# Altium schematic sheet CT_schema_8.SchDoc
size 254 x 194 mm
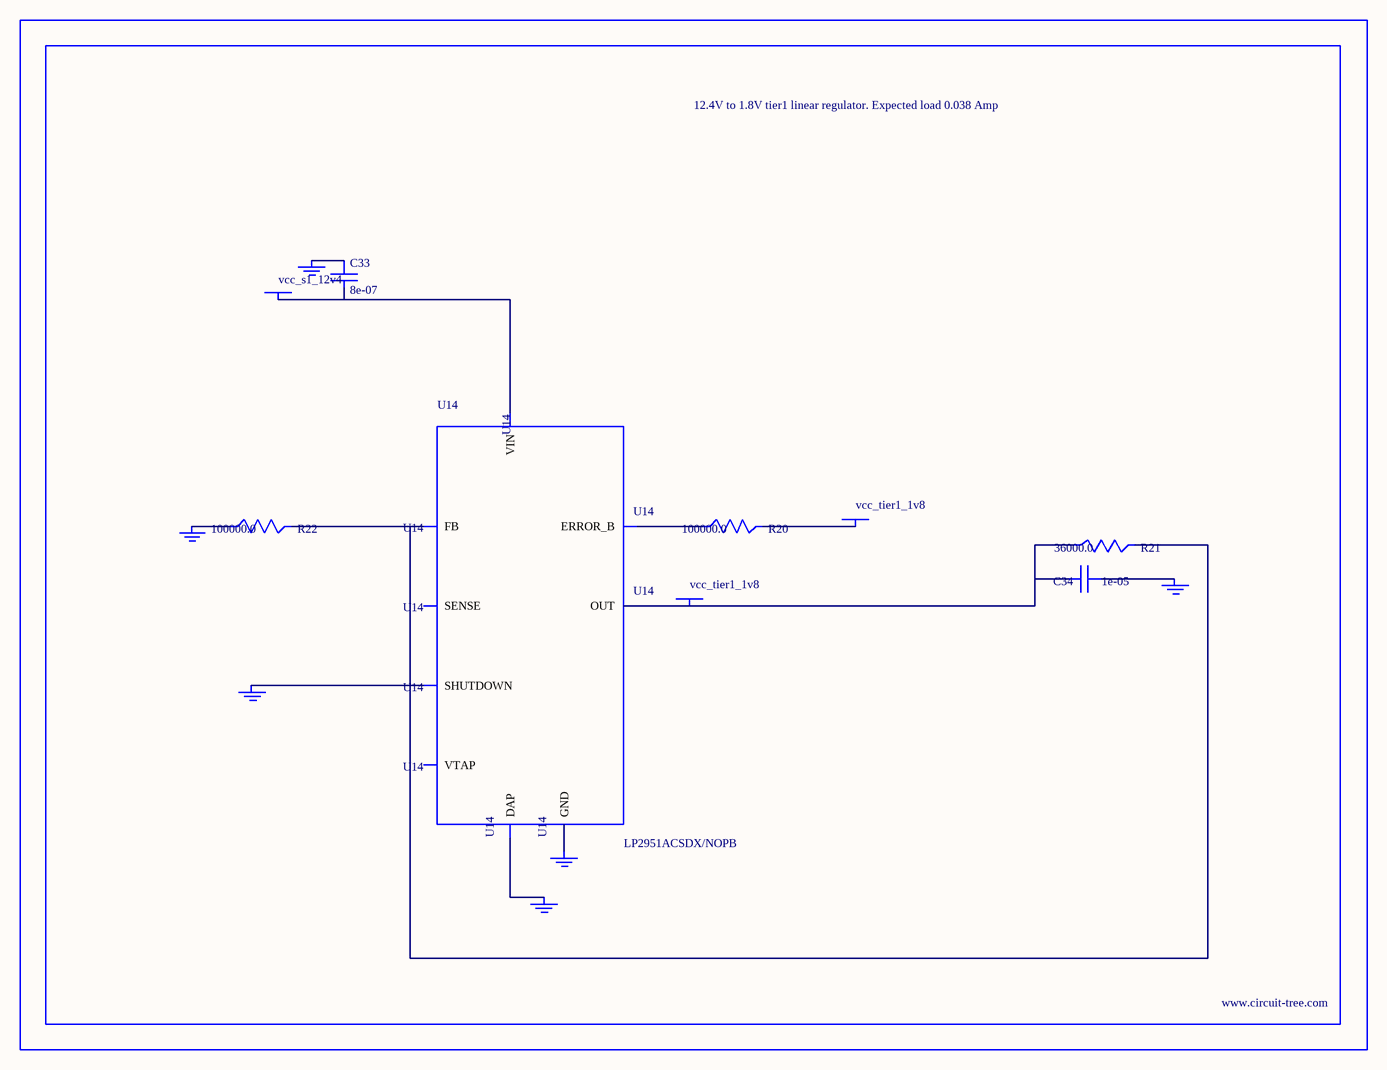
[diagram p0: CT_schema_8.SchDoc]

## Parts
BORDER7  (no value)
C33  8e-07  [R0603]
C34  1e-05  [C0805]
GND_INSTANCE_7_0  (no value)
GND_INSTANCE_7_1  (no value)
GND_INSTANCE_7_2  (no value)
GND_INSTANCE_7_3  (no value)
GND_INSTANCE_7_4  (no value)
GND_INSTANCE_7_5  (no value)
POWER_INSTANCE_7_0  vcc_tier1_1v8
POWER_INSTANCE_7_1  vcc_s1_12v4
POWER_INSTANCE_7_2  vcc_tier1_1v8
R20  100000.0  [R0603]
R21  36000.0  [R0603]
R22  100000.0  [R0603]
U14  LP2951ACSDX/NOPB  [WSON-8]

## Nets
NetC33_1: C33.1 GND_INSTANCE_7_3.0(GND)
NetC33_2: C33.2 POWER_INSTANCE_7_1.0(PWR) U14.8(VIN)
NetC34_1: C34.1 GND_INSTANCE_7_0.0(GND)
NetC34_2: C34.2 POWER_INSTANCE_7_2.0(PWR) R21.1 U14.1(OUT)
NetGND_INSTANCE_7_1_0: GND_INSTANCE_7_1.0(GND) U14.3(SHUTDOWN)
NetGND_INSTANCE_7_2_0: GND_INSTANCE_7_2.0(GND) R22.1
NetGND_INSTANCE_7_4_0: GND_INSTANCE_7_4.0(GND) U14.PAD(DAP)
NetGND_INSTANCE_7_5_0: GND_INSTANCE_7_5.0(GND) U14.4(GND)
NetPOWER_INSTANCE_7_0_0: POWER_INSTANCE_7_0.0(PWR) R20.2
NetR20_1: R20.1 U14.5(ERROR_B)
NetR21_2: R21.2 R22.2 U14.7(FB)

Not connected (* = marked no-connect by the designer): U14 2(SENSE) 6(VTAP)

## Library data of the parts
BORDER7 = BORDER_PAGE7
C33 = C33
C34 = GRM219R60J106ME19D
GND_INSTANCE_7_0-GND_INSTANCE_7_5 = GND
POWER_INSTANCE_7_0-POWER_INSTANCE_7_2 = PWR
R20 R22 = RC0603JR-07100KL
R21 = RC0603JR-0736KL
